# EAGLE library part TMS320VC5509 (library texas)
TMS320VC5509A Fixed-Point Digital Signal Processor Auto generated by make-symbol-device-package-bsdl.ulp Rev. 30 Source: sprm155a.bsm http://focus.ti.com/lit/ds/symlink/tms320vc5509a.pdf Connect-List generated from TMS320VC5509A.DEV Variant '' with connect-device-split-symbol.ulp
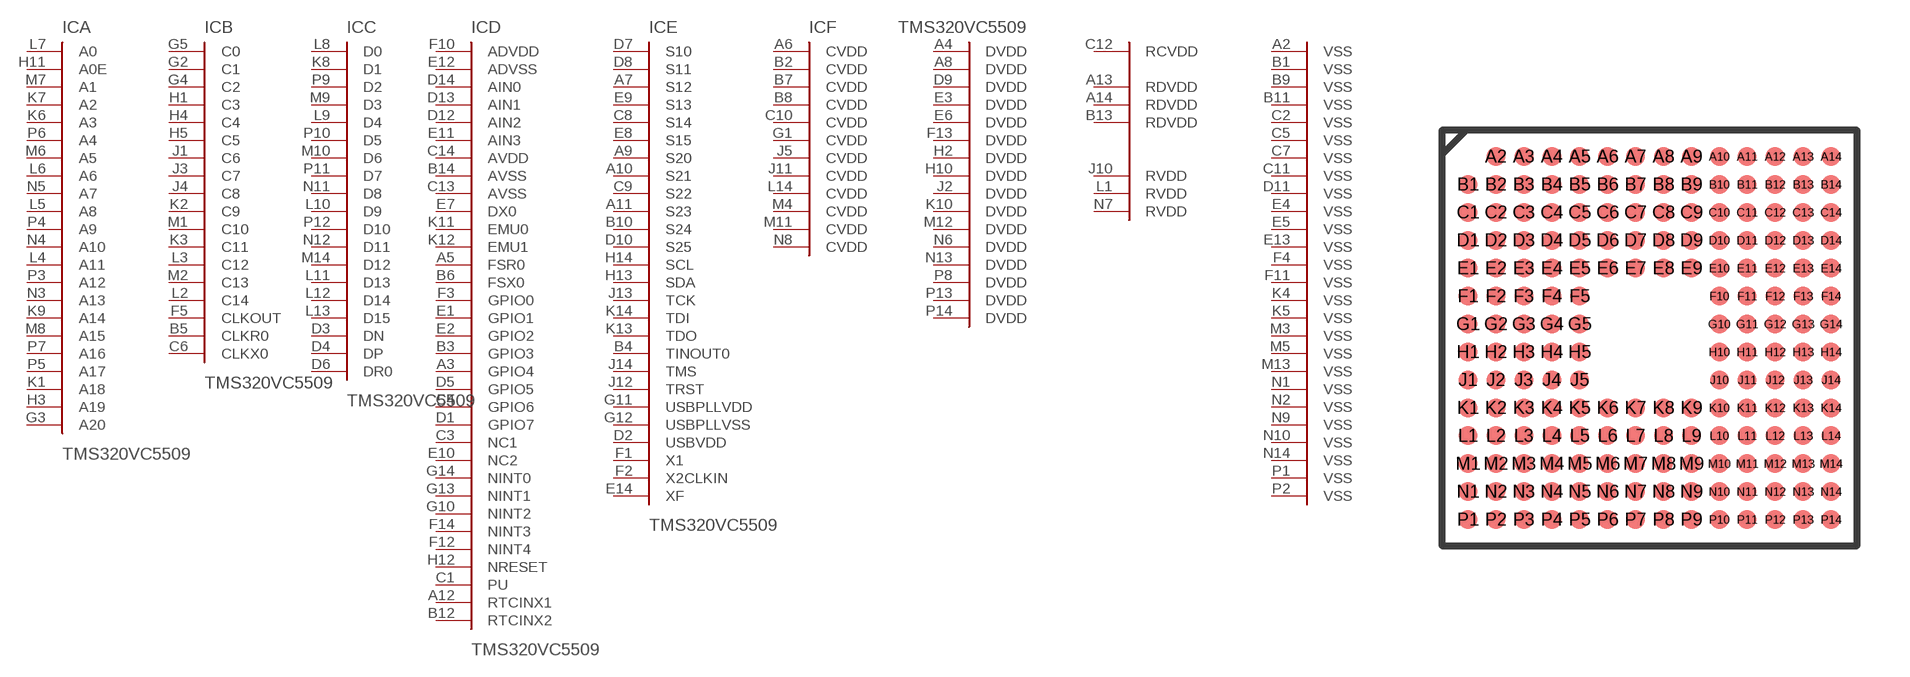
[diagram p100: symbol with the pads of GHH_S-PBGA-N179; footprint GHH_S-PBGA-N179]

Designator prefix IC; gates A=TMS320VC5509-A B=TMS320VC5509-B D=TMS320VC5509-D E=TMS320VC5509-E C=TMS320VC5509-C F=TMS320VC5509-P

## TMS320VC5509 (MPN: TMS320VC5509AGHH; OC_FARNELL: 1610194; OC_NEWARK: 14N9600)  [GHH_S-PBGA-N179]
A2  F:VSS  pwr
A3  D:GPIO4
A4  F:DVDD  pwr
A5  D:FSR0
A6  F:CVDD  pwr
A7  E:S12
A8  F:DVDD  pwr
A9  E:S20
A10  E:S21
A11  E:S23
A12  D:RTCINX1  pas
A13  F:RDVDD  pwr
A14  F:RDVDD  pwr
B1  F:VSS  pwr
B2  F:CVDD  pwr
B3  D:GPIO3
B4  E:TINOUT0
B5  B:CLKR0
B6  D:FSX0
B7  F:CVDD  pwr
B8  F:CVDD  pwr
B9  F:VSS  pwr
B10  E:S24
B11  F:VSS  pwr
B12  D:RTCINX2  pas
B13  F:RDVDD  pwr
B14  D:AVSS  pwr
C1  D:PU  pas
C2  F:VSS  pwr
C3  D:NC1  pas
C4  D:GPIO6
C5  F:VSS  pwr
C6  B:CLKX0
C7  F:VSS  pwr
C8  E:S14
C9  E:S22
C10  F:CVDD  pwr
C11  F:VSS  pwr
C12  F:RCVDD  pwr
C13  D:AVSS  pwr
C14  D:AVDD  pwr
D1  D:GPIO7
D2  E:USBVDD  pwr
D3  C:DN  pas
D4  C:DP  pas
D5  D:GPIO5
D6  C:DR0  in
D7  E:S10
D8  E:S11
D9  F:DVDD  pwr
D10  E:S25
D11  F:VSS  pwr
D12  D:AIN2  pas
D13  D:AIN1  pas
D14  D:AIN0  pas
E1  D:GPIO1
E2  D:GPIO2
E3  F:DVDD  pwr
E4  F:VSS  pwr
E5  F:VSS  pwr
E6  F:DVDD  pwr
E7  D:DX0  out
E8  E:S15
E9  E:S13
E10  D:NC2  pas
E11  D:AIN3  pas
E12  D:ADVSS  pwr
E13  F:VSS  pwr
E14  E:XF  out
F1  E:X1  pas
F2  E:X2CLKIN  in
F3  D:GPIO0
F4  F:VSS  pwr
F5  B:CLKOUT  out
F10  D:ADVDD  pwr
F11  F:VSS  pwr
F12  D:NINT4  in
F13  F:DVDD  pwr
F14  D:NINT3  in
G1  F:CVDD  pwr
G2  B:C1  out
G3  A:A20  out
G4  B:C2
G5  B:C0
G10  D:NINT2  in
G11  E:USBPLLVDD  pwr
G12  E:USBPLLVSS  pwr
G13  D:NINT1  in
G14  D:NINT0  in
H1  B:C3
H2  F:DVDD  pwr
H3  A:A19  out
H4  B:C4
H5  B:C5
H10  F:DVDD  pwr
H11  A:A0E  out
H12  D:NRESET  in
H13  E:SDA
H14  E:SCL
J1  B:C6
J2  F:DVDD  pwr
J3  B:C7
J4  B:C8
J5  F:CVDD  pwr
J10  F:RVDD  pwr
J11  F:CVDD  pwr
J12  E:TRST  in
J13  E:TCK  in
J14  E:TMS  in
K1  A:A18  out
K2  B:C9
K3  B:C11
K4  F:VSS  pwr
K5  F:VSS  pwr
K6  A:A3
K7  A:A2
K8  C:D1
K9  A:A14
K10  F:DVDD  pwr
K11  D:EMU0  in
K12  D:EMU1  in
K13  E:TDO  out
K14  E:TDI  in
L1  F:RVDD  pwr
L2  B:C14
L3  B:C12
L4  A:A11
L5  A:A8
L6  A:A6
L7  A:A0
L8  C:D0
L9  C:D4
L10  C:D9
L11  C:D13
L12  C:D14
L13  C:D15
L14  F:CVDD  pwr
M1  B:C10
M2  B:C13
M3  F:VSS  pwr
M4  F:CVDD  pwr
M5  F:VSS  pwr
M6  A:A5
M7  A:A1
M8  A:A15
M9  C:D3
M10  C:D6
M11  F:CVDD  pwr
M12  F:DVDD  pwr
M13  F:VSS  pwr
M14  C:D12
N1  F:VSS  pwr
N2  F:VSS  pwr
N3  A:A13
N4  A:A10
N5  A:A7
N6  F:DVDD  pwr
N7  F:RVDD  pwr
N8  F:CVDD  pwr
N9  F:VSS  pwr
N10  F:VSS  pwr
N11  C:D8
N12  C:D11
N13  F:DVDD  pwr
N14  F:VSS  pwr
P1  F:VSS  pwr
P2  F:VSS  pwr
P3  A:A12
P4  A:A9
P5  A:A17  out
P6  A:A4
P7  A:A16  out
P8  F:DVDD  pwr
P9  C:D2
P10  C:D5
P11  C:D7
P12  C:D10
P13  F:DVDD  pwr
P14  F:DVDD  pwr

## Footprint GHH_S-PBGA-N179 (pad centres in mm)
GHH (S-PBGA-N179) Auto generated by make-symbol-device-package-bsdl.ulp Rev. 30 Source: sprm155a.bsm http://focus.ti.com/lit/ds/symlink/tms320vc5509a.pdf
smd 0.55 x 0.55: A2 -4.4,5.2; A3 -3.6,5.2; A4 -2.8,5.2; A5 -2,5.2; A6 -1.2,5.2; A7 -0.4,5.2; A8 0.4,5.2; A9 1.2,5.2; A10 2,5.2; A11 2.8,5.2; A12 3.6,5.2; A13 4.4,5.2; A14 5.2,5.2; B1 -5.2,4.4; B2 -4.4,4.4; B3 -3.6,4.4; B4 -2.8,4.4; B5 -2,4.4; B6 -1.2,4.4; B7 -0.4,4.4; B8 0.4,4.4; B9 1.2,4.4; B10 2,4.4; B11 2.8,4.4; B12 3.6,4.4; B13 4.4,4.4; B14 5.2,4.4; C1 -5.2,3.6; C2 -4.4,3.6; C3 -3.6,3.6; C4 -2.8,3.6; C5 -2,3.6; C6 -1.2,3.6; C7 -0.4,3.6; C8 0.4,3.6; C9 1.2,3.6; C10 2,3.6; C11 2.8,3.6; C12 3.6,3.6; C13 4.4,3.6; C14 5.2,3.6; D1 -5.2,2.8; D2 -4.4,2.8; D3 -3.6,2.8; D4 -2.8,2.8; D5 -2,2.8; D6 -1.2,2.8; D7 -0.4,2.8; D8 0.4,2.8; D9 1.2,2.8; D10 2,2.8; D11 2.8,2.8; D12 3.6,2.8; D13 4.4,2.8; D14 5.2,2.8; E1 -5.2,2; E2 -4.4,2; E3 -3.6,2; E4 -2.8,2; E5 -2,2; E6 -1.2,2; E7 -0.4,2; E8 0.4,2; E9 1.2,2; E10 2,2; E11 2.8,2; E12 3.6,2; E13 4.4,2; E14 5.2,2; F1 -5.2,1.2; F2 -4.4,1.2; F3 -3.6,1.2; F4 -2.8,1.2; F5 -2,1.2; F10 2,1.2; F11 2.8,1.2; F12 3.6,1.2; F13 4.4,1.2; F14 5.2,1.2; G1 -5.2,0.4; G2 -4.4,0.4; G3 -3.6,0.4; G4 -2.8,0.4; G5 -2,0.4; G10 2,0.4; G11 2.8,0.4; G12 3.6,0.4; G13 4.4,0.4; G14 5.2,0.4; H1 -5.2,-0.4; H2 -4.4,-0.4; H3 -3.6,-0.4; H4 -2.8,-0.4; H5 -2,-0.4; H10 2,-0.4; H11 2.8,-0.4; H12 3.6,-0.4; H13 4.4,-0.4; H14 5.2,-0.4; J1 -5.2,-1.2; J2 -4.4,-1.2; J3 -3.6,-1.2; J4 -2.8,-1.2; J5 -2,-1.2; J10 2,-1.2; J11 2.8,-1.2; J12 3.6,-1.2; J13 4.4,-1.2; J14 5.2,-1.2; K1 -5.2,-2; K2 -4.4,-2; K3 -3.6,-2; K4 -2.8,-2; K5 -2,-2; K6 -1.2,-2; K7 -0.4,-2; K8 0.4,-2; K9 1.2,-2; K10 2,-2; K11 2.8,-2; K12 3.6,-2; K13 4.4,-2; K14 5.2,-2; L1 -5.2,-2.8; L2 -4.4,-2.8; L3 -3.6,-2.8; L4 -2.8,-2.8; L5 -2,-2.8; L6 -1.2,-2.8; L7 -0.4,-2.8; L8 0.4,-2.8; L9 1.2,-2.8; L10 2,-2.8; L11 2.8,-2.8; L12 3.6,-2.8; L13 4.4,-2.8; L14 5.2,-2.8; M1 -5.2,-3.6; M2 -4.4,-3.6; M3 -3.6,-3.6; M4 -2.8,-3.6; M5 -2,-3.6; M6 -1.2,-3.6; M7 -0.4,-3.6; M8 0.4,-3.6; M9 1.2,-3.6; M10 2,-3.6; M11 2.8,-3.6; M12 3.6,-3.6; M13 4.4,-3.6; M14 5.2,-3.6; N1 -5.2,-4.4; N2 -4.4,-4.4; N3 -3.6,-4.4; N4 -2.8,-4.4; N5 -2,-4.4; N6 -1.2,-4.4; N7 -0.4,-4.4; N8 0.4,-4.4; N9 1.2,-4.4; N10 2,-4.4; N11 2.8,-4.4; N12 3.6,-4.4; N13 4.4,-4.4; N14 5.2,-4.4; P1 -5.2,-5.2; P2 -4.4,-5.2; P3 -3.6,-5.2; P4 -2.8,-5.2; P5 -2,-5.2; P6 -1.2,-5.2; P7 -0.4,-5.2; P8 0.4,-5.2; P9 1.2,-5.2; P10 2,-5.2; P11 2.8,-5.2; P12 3.6,-5.2; P13 4.4,-5.2; P14 5.2,-5.2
